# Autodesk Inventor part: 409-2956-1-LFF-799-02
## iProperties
Created: 2010-11
Part Number: 409-2956-1-LFF-799-02
Material: 3/4" OD TUBE - SS
Document SubType Name: Modeling
Designer: S. Boerckel
Engineer: Steve Boerckel
Mass: 309.983 g
Surface Area: 466.545 cm^2
Volume: 38.3643 cm^3
Density: 8.08 g/cm^3
Description: DRAIN TUBING
Length: 16.737 in
Author: S. Boerckel
Revision Number: 0
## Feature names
1. Sweep1
